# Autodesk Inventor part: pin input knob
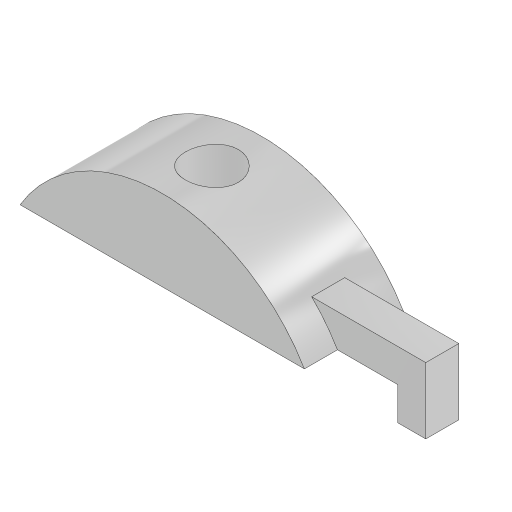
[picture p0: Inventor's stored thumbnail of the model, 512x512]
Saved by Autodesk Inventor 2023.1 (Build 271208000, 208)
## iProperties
Created: 2020-02
Part Number: pin input knob
Material: Aluminum 6061
Document SubType Name: Modeling
Designer: ftrauzettel
Density: 2.7 g/cm^3
Appearance: Aluminum - Polished
Sending System: SolidWorks 2016
Last Author: Pam
Last Saved: 2020-02-27
Author: ftrauzettel
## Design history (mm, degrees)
feature "Tap Drill Slot for M2 Tap1"
body "Solid1"
